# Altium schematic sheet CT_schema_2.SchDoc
size 461 x 327 mm
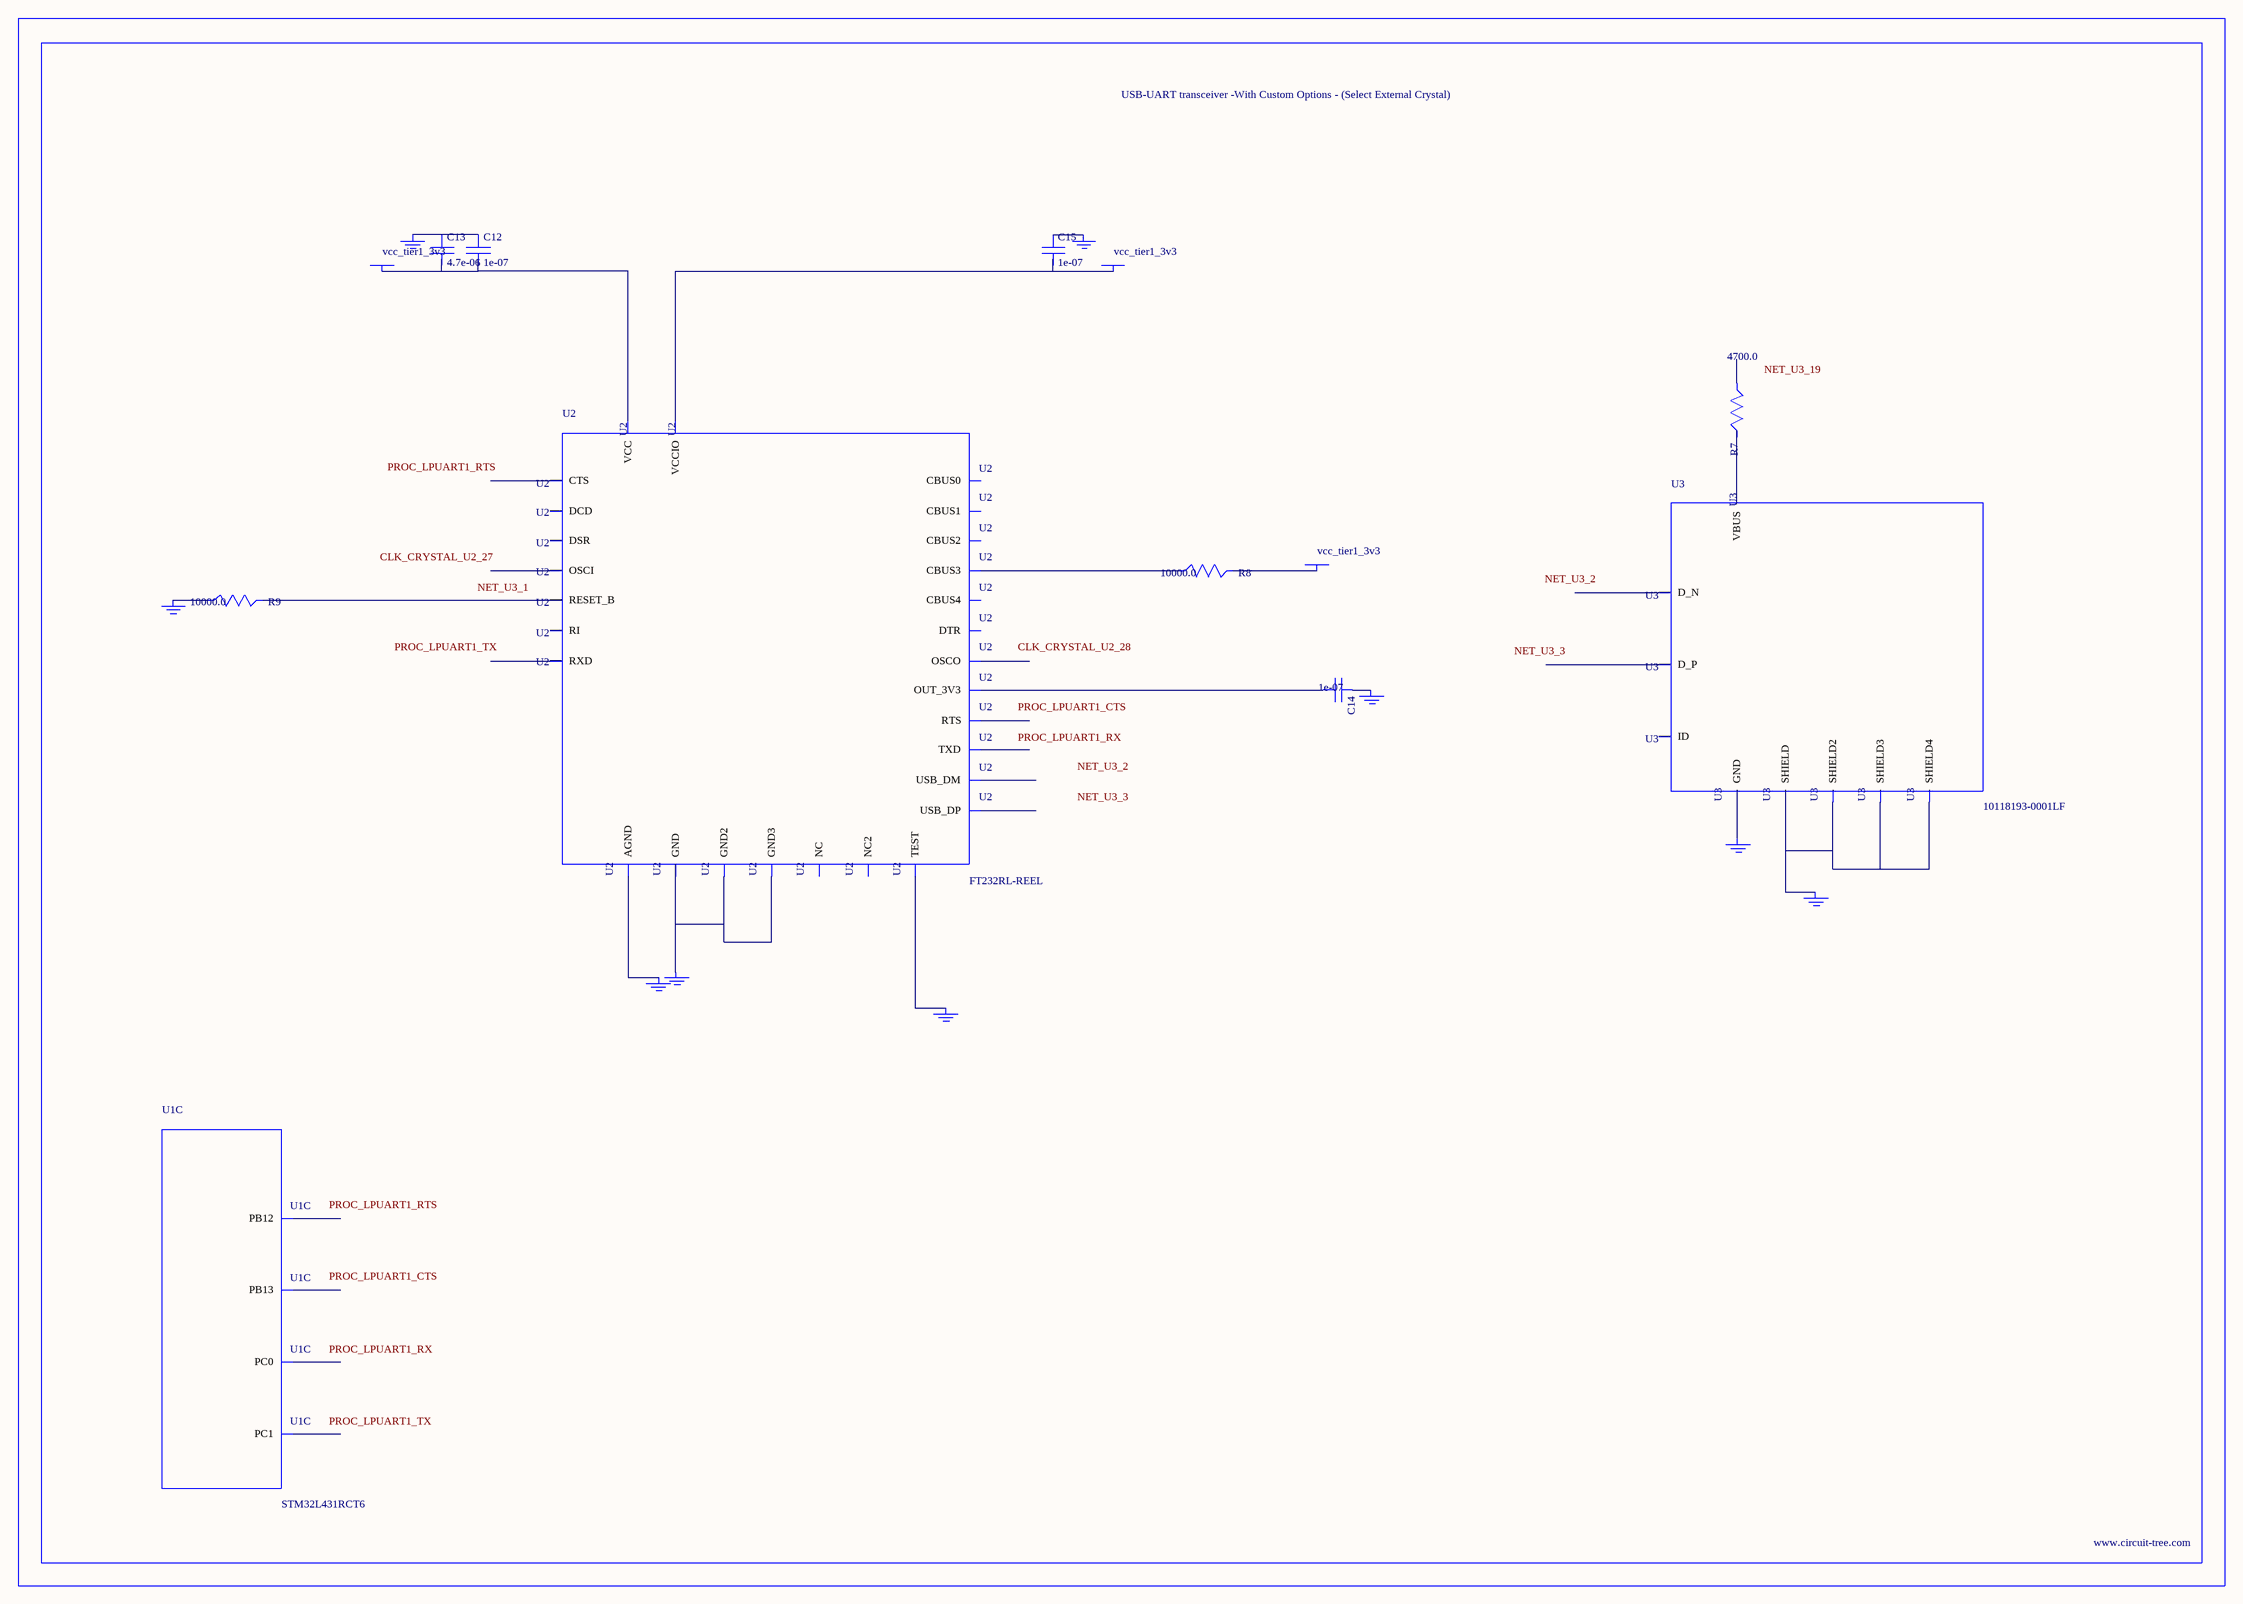
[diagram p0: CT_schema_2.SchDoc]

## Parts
BORDER1  (no value)
C12  1e-07  [C0402]
C13  4.7e-06  [C0805]
C14  1e-07  [C0402]
C15  1e-07  [C0402]
GND_INSTANCE_1_0  (no value)
GND_INSTANCE_1_1  (no value)
GND_INSTANCE_1_2  (no value)
GND_INSTANCE_1_3  (no value)
GND_INSTANCE_1_4  (no value)
GND_INSTANCE_1_5  (no value)
GND_INSTANCE_1_6  (no value)
GND_INSTANCE_1_7  (no value)
GND_INSTANCE_1_8  (no value)
POWER_INSTANCE_1_0  vcc_tier1_3v3
POWER_INSTANCE_1_1  vcc_tier1_3v3
POWER_INSTANCE_1_2  vcc_tier1_3v3
R7  4700.0  [R0603]
R8  10000.0  [R0603]
R9  10000.0  [R0603]
U1  STM32L431RCT6  [LQFP64]  (part C of 6)
U2  FT232RL-REEL  [SSOP-28]
U3  10118193-0001LF  [FCI_10118193-0001LF]

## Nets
NetC12_1: C12.1 C13.1 GND_INSTANCE_1_3.0(GND)
NetC12_2: C12.2 C13.2 POWER_INSTANCE_1_2.0(PWR) U2.20(VCC)
NetC14_1: C14.1 GND_INSTANCE_1_1.0(GND)
NetC14_2: C14.2 U2.17(OUT_3V3)
NetC15_1: C15.1 GND_INSTANCE_1_0.0(GND)
NetC15_2: C15.2 POWER_INSTANCE_1_0.0(PWR) U2.4(VCCIO)
NetGND_INSTANCE_1_2_0: GND_INSTANCE_1_2.0(GND) R9.1
NetGND_INSTANCE_1_4_0: GND_INSTANCE_1_4.0(GND) U2.25(AGND)
NetGND_INSTANCE_1_5_0: GND_INSTANCE_1_5.0(GND) U2.26(TEST)
NetGND_INSTANCE_1_6_0: GND_INSTANCE_1_6.0(GND) U2.7(GND) U2.18(GND2) U2.21(GND3)
NetGND_INSTANCE_1_7_0: GND_INSTANCE_1_7.0(GND) U3.6(SHIELD) U3.7(SHIELD2) U3.8(SHIELD3) U3.9(SHIELD4)
NetGND_INSTANCE_1_8_0: GND_INSTANCE_1_8.0(GND) U3.5(GND)
NetPOWER_INSTANCE_1_1_0: POWER_INSTANCE_1_1.0(PWR) R8.2
NetR7_2: R7.2 U3.1(VBUS)
NetR8_1: R8.1 U2.14(CBUS3)
NetR9_2: R9.2 U2.19(RESET_B)

Not connected (* = marked no-connect by the designer): R7 1; U1 8(PC0) 9(PC1) 33(PB12) 34(PB13); U2 1(TXD) 2(DTR) 3(RTS) 5(RXD) 6(RI) 8(NC) 9(DSR) 10(DCD) 11(CTS) 12(CBUS4) 13(CBUS2) 15(USB_DP) 16(USB_DM) 22(CBUS1) 23(CBUS0) 24(NC2) 27(OSCI) 28(OSCO); U3 2(D_N) 3(D_P) 4(ID)

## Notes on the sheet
- Labels drawn without touching a wire or pin: CLK_CRYSTAL_U2_27, CLK_CRYSTAL_U2_28, NET_U3_1, NET_U3_2, NET_U3_3, NET_U3_19, PROC_LPUART1_CTS, PROC_LPUART1_RTS, PROC_LPUART1_RX, PROC_LPUART1_TX

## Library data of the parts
BORDER1 = BORDER_PAGE1
C12 C14 C15 = C0402C104K3RACTU
C13 = C0805C475K4RACTU
GND_INSTANCE_1_0-GND_INSTANCE_1_8 = GND
POWER_INSTANCE_1_0-POWER_INSTANCE_1_2 = PWR
R7 = RC0603JR-074K7L
R8 R9 = RC0603JR-0710KL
